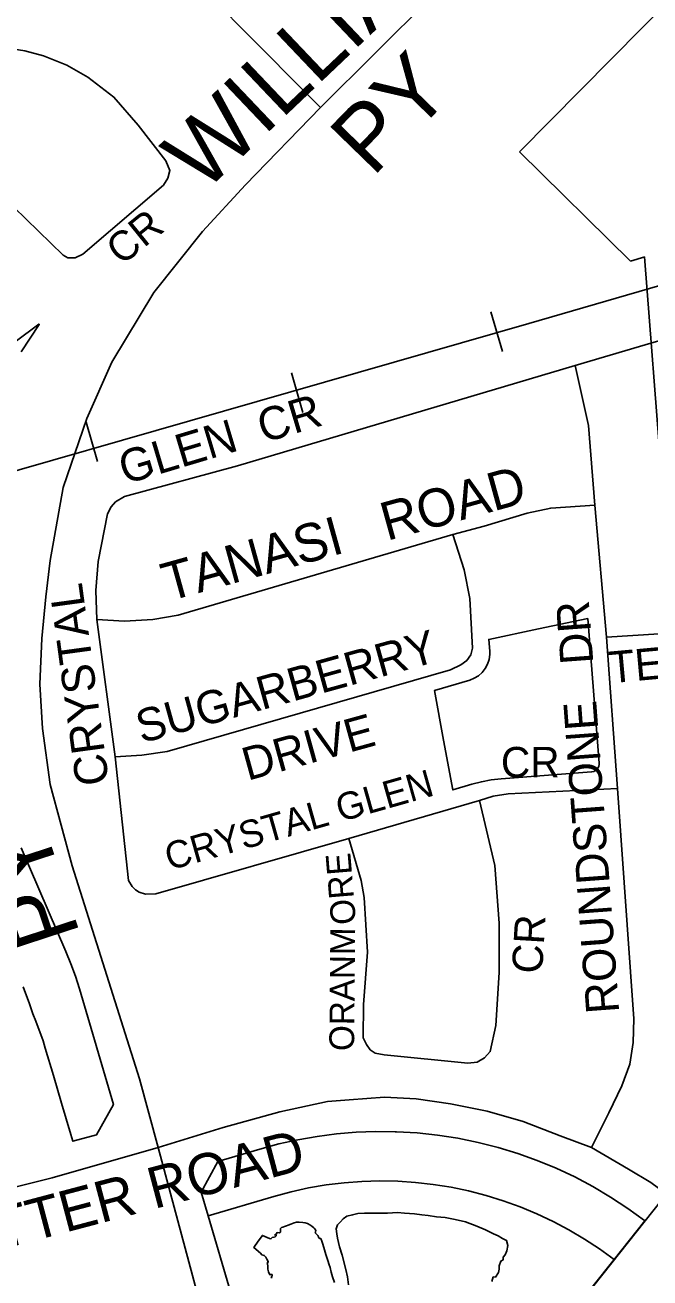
# Model space of a CAD drawing. Extents: x 586326 to 623965, y 4819854 to 4857850.
# Drawn here: x 596152 to 596531, y 4836331 to 4837091 of the extents above; entities that cross this region are included whole.
import ezdxf

# ---------------------------------------------------------------- set-up
doc = ezdxf.new("R2010")
doc.units = 0
for name, color, linetype in [('Hydro ROW', 7, 'Continuous'), ('Lots_Concessions', 7, 'Continuous'), ('Major Rds and Hwys', 7, 'Continuous'), ('Major Rds Lbls', 7, 'Continuous'), ('Minor Rd Lbls', 7, 'Continuous'), ('Minor Rds', 7, 'Continuous'), ('Park Outlines', 7, 'Continuous'), ('Proposed Secondary Rds', 7, 'Continuous'), ('Railways_lbls', 7, 'Continuous'), ('SWM Ponds', 7, 'Continuous')]:
    doc.layers.add(name, color=color, linetype=linetype)

msp = doc.modelspace()

# ---------------------------------------------------------------- linework, layer by layer
at = {"layer": 'Hydro ROW'}
for p, q in [((596591.02, 4837155.19), (596451.94, 4837014.18)), ((596451.94, 4837014.18), (596519.14, 4836947.9)), ((596519.14, 4836947.9), (596527.85, 4836950.48)), ((596563.94, 4836481.91), (596527.79, 4836950.49))]:
    msp.add_line(p, q, dxfattribs=at)
at = {"layer": 'Lots_Concessions'}
msp.add_line((596484.66, 4836310.94), (596595.56, 4836450.63), dxfattribs=at)
at = {"layer": 'Major Rds and Hwys'}
for points in [[(596331.19, 4837041.21), (596397.85, 4837107.73), (596397.99, 4837107.88)], [(596167.02, 4836766.26), (596174.85, 4836810.5), (596189.29, 4836852.37), (596204.48, 4836886.5), (596230.05, 4836928.93), (596259.56, 4836965.95), (596285.65, 4836994.14), (596331.19, 4837041.21)], [(596232.55, 4836410.04), (596221.35, 4836451.78), (596180.34, 4836580.86), (596167.06, 4836630.21), (596162.45, 4836664.21), (596160.75, 4836691.28), (596162.09, 4836718.92), (596164.36, 4836744.15), (596167.02, 4836766.26)], [(596495.59, 4836410.01), (596476.56, 4836417.2), (596454.05, 4836425.89), (596432.2, 4836432.06), (596409.99, 4836436.47), (596389.09, 4836439.47), (596369.91, 4836440.51), (596348.54, 4836439.02), (596335.34, 4836437.93), (596306.45, 4836431.7), (596272.05, 4836422.25), (596232.55, 4836410.04)], [(596232.55, 4836410.04), (596168.29, 4836391.6), (596113.61, 4836377.99), (596057.04, 4836366.29), (595995.22, 4836356.51), (595946.67, 4836348.86)], [(596308.02, 4836117.6), (596304.64, 4836135.97), (596301.26, 4836154.34), (596232.55, 4836410.04)], [(596540.91, 4836381.9), (596531.48, 4836388.76), (596518.05, 4836396.88), (596495.59, 4836410.01)]]:
    msp.add_lwpolyline(points, dxfattribs=at)
at = {"layer": 'Minor Rds'}
for points in [[(596177.73, 4836949.97), (596174.97, 4836951.5), (596144.95, 4836980.58), (596139.29, 4836984.8), (596134.12, 4836987.79), (596129.38, 4836990.25), (596124.6, 4836991.07), (596099.83, 4836996.45), (596095.34, 4836998.71), (596092.74, 4837001.56), (596090.58, 4837006.11), (596090.87, 4837011.35), (596101.52, 4837083.46)], [(596177.73, 4836949.97), (596182.3, 4836949.95), (596186.84, 4836952.02), (596235.73, 4836994.06), (596238.37, 4836998.25), (596239.68, 4837002.86), (596237.16, 4837008.67), (596220.51, 4837030.34), (596205.74, 4837047.39), (596190.01, 4837059.59), (596177.08, 4837066.77), (596163.03, 4837072.54), (596151.75, 4837075.46), (596113.92, 4837081.46), (596101.52, 4837083.46)], [(596485.72, 4836884.52), (596524.79, 4836896.14), (596546.68, 4836902.65), (596603.47, 4836918.93)], [(596195.3, 4836730.51), (596194.8, 4836748.1), (596196.12, 4836765.62), (596201.78, 4836794.53), (596204.11, 4836798.89), (596206.75, 4836801.93), (596212.11, 4836805), (596280.83, 4836823.68), (596485.72, 4836884.52)], [(596497.5, 4836799.75), (596493.68, 4836848.07), (596485.72, 4836884.52)], [(596497.5, 4836799.75), (596470.86, 4836797.99), (596456.6, 4836794.88), (596430.39, 4836787.14), (596411.39, 4836782.09)], [(596504.68, 4836719.75), (596497.5, 4836799.75)], [(596411.39, 4836782.09), (596244.8, 4836732.96), (596229.41, 4836730.47), (596212.19, 4836729.41), (596195.3, 4836730.51)], [(596411.39, 4836782.09), (596418.27, 4836760.48), (596421.72, 4836743.09), (596423.44, 4836713.11), (596422.42, 4836708.99), (596420, 4836705.56), (596416.32, 4836703), (596409.94, 4836699.94), (596238.08, 4836650.36), (596222.77, 4836648.14), (596206.53, 4836647.03)], [(596206.53, 4836647.03), (596195.3, 4836730.51)], [(596621.32, 4836728.19), (596601.41, 4836725.53), (596586.06, 4836724.73), (596552.56, 4836722.68), (596504.68, 4836719.75)], [(596511.26, 4836627.9), (596504.68, 4836719.75)], [(596348.29, 4836597.46), (596231.24, 4836563.94), (596224.81, 4836563.83), (596221.12, 4836564.9), (596218.76, 4836566.33), (596216.74, 4836568.45), (596214.65, 4836572.07), (596206.53, 4836647.03)], [(596511.26, 4836627.9), (596444.95, 4836624.58), (596435.98, 4836623.14), (596427.65, 4836620.6)], [(596495.59, 4836410.01), (596506.16, 4836431.04), (596513.91, 4836447.42), (596518.88, 4836460.51), (596520.77, 4836473.78), (596521.17, 4836488.01), (596511.26, 4836627.9)], [(596427.65, 4836620.6), (596436.91, 4836581.06), (596439.5, 4836546.13), (596439.62, 4836516.15), (596437.47, 4836484.02), (596434.16, 4836468.2), (596430.56, 4836464.36), (596426.13, 4836461.79), (596420.6, 4836461.28), (596369.83, 4836466.23), (596364.28, 4836467.24), (596361.33, 4836469.25), (596359.06, 4836472.53), (596357.04, 4836476.52), (596357.25, 4836496.88), (596359.64, 4836528.53), (596357.58, 4836561.83), (596355.83, 4836571.95), (596348.29, 4836597.46)], [(596427.65, 4836620.6), (596348.29, 4836597.46)]]:
    msp.add_lwpolyline(points, dxfattribs=at)
at = {"layer": 'Park Outlines'}
for points in [[(596149.52, 4836892.78), (596160.43, 4836909.53), (596160.22, 4836909.74), (596132.05, 4836888.75)], [(596150.64, 4836507.47), (596154.43, 4836497.11), (596156.63, 4836491.09), (596158.26, 4836486.78), (596162.81, 4836474.78), (596164.1, 4836470.36), (596169.02, 4836453.67), (596173.93, 4836436.98), (596179.56, 4836417.83), (596180.75, 4836413.8), (596195.23, 4836417.72), (596205.44, 4836436.15), (596184.82, 4836506.23), (596182.38, 4836513.93), (596179.64, 4836521.53), (596176.58, 4836529.01), (596149.41, 4836591.96)], [(596484.63, 4836311.03), (596509.25, 4836342.04), (596500.42, 4836348.47), (596491.3, 4836354.48), (596481.9, 4836360.05), (596472.25, 4836365.18), (596462.38, 4836369.84), (596452.29, 4836374.03), (596442.02, 4836377.75), (596431.58, 4836380.97), (596421, 4836383.7), (596410.31, 4836385.93), (596399.58, 4836387.65), (596388.79, 4836388.86), (596377.95, 4836389.57), (596367.09, 4836389.76), (596356.23, 4836389.45), (596345.4, 4836388.63), (596334.62, 4836387.3), (596323.91, 4836385.47), (596313.3, 4836383.15), (596302.81, 4836380.32), (596262.85, 4836368.56), (596276.43, 4836322.41)]]:
    msp.add_lwpolyline(points, dxfattribs=at)
for points in [[(596493.41, 4836731.12), (596463.31, 4836724.75), (596433.23, 4836718.39), (596433.78, 4836711.25), (596433.82, 4836709.23), (596433.42, 4836706.25), (596432.51, 4836703.37), (596431.11, 4836700.71), (596429.25, 4836698.33), (596427.01, 4836696.32), (596424.44, 4836694.74), (596421.64, 4836693.63), (596400.36, 4836687.36), (596405.85, 4836657.2), (596411.34, 4836627.03), (596422.9, 4836630.44), (596428.78, 4836631.95), (596434.75, 4836633.05), (596440.78, 4836633.73), (596495.59, 4836637.96), (596497.01, 4836638.28), (596498.27, 4836638.99), (596499.27, 4836640.03), (596499.94, 4836641.32), (596500.2, 4836642.74), (596500.19, 4836643.33)], [(596410.31, 4836385.93), (596421, 4836383.7), (596431.58, 4836380.97), (596442.02, 4836377.75), (596452.29, 4836374.03), (596462.38, 4836369.84), (596472.25, 4836365.18), (596481.9, 4836360.05), (596491.3, 4836354.48), (596500.42, 4836348.47), (596509.25, 4836342.04), (596527.9, 4836365.53), (596527.82, 4836365.59), (596527.74, 4836365.65), (596527.66, 4836365.72), (596517.58, 4836373.07), (596507.15, 4836379.94), (596496.41, 4836386.3), (596485.38, 4836392.14), (596474.09, 4836397.45), (596462.55, 4836402.22), (596450.8, 4836406.43), (596438.86, 4836410.08), (596426.76, 4836413.15), (596414.53, 4836415.65), (596402.2, 4836417.56), (596389.78, 4836418.88), (596377.32, 4836419.6), (596376.89, 4836419.62), (596376.45, 4836419.63), (596364.58, 4836419.73), (596352.71, 4836419.29), (596340.88, 4836418.32), (596329.1, 4836416.8), (596317.4, 4836414.76), (596305.81, 4836412.19), (596294.34, 4836409.09), (596268.77, 4836401.56), (596258.62, 4836382.94), (596262.85, 4836368.56), (596302.81, 4836380.32), (596313.3, 4836383.15), (596323.91, 4836385.47), (596334.62, 4836387.3), (596345.4, 4836388.63), (596356.23, 4836389.45), (596367.09, 4836389.76), (596377.95, 4836389.57), (596388.79, 4836388.86), (596399.58, 4836387.65)]]:
    msp.add_lwpolyline(points, close=True, dxfattribs=at)
at = {"layer": 'Proposed Secondary Rds'}
msp.add_lwpolyline([(596331.19, 4837041.21), (596280.91, 4837091.39), (596273.96, 4837098.83)], dxfattribs=at)
at = {"layer": 'Railways_lbls'}
for p, q in [((596434.48, 4836917.1), (596441.48, 4836893.1)), ((596313.48, 4836880.1), (596320.48, 4836856.1)), ((596188.87, 4836850.25), (596195.87, 4836826.25))]:
    msp.add_line(p, q, dxfattribs=at)
msp.add_lwpolyline([(598326.48, 4837460.1), (597795.48, 4837305.1), (597795.48, 4837304.1), (597377.48, 4837181.1), (597375.48, 4837181.1), (596913.48, 4837043.1), (596909.48, 4837041.1), (596457.48, 4836910.1), (595921.93, 4836756.32)], dxfattribs=at)
at = {"layer": 'SWM Ponds'}
for points in [[(596339.69, 4836328.2), (596338.38, 4836331.52), (596337.59, 4836334.33), (596336.9, 4836337.28), (596336.33, 4836338.73), (596335.49, 4836341.42), (596334.37, 4836345.18), (596333.63, 4836348), (596332.57, 4836351.28), (596331.97, 4836353.19), (596331.3, 4836354.79), (596330.65, 4836354.71), (596330.11, 4836355.18), (596329.87, 4836355.9), (596329.57, 4836356.67), (596328.6, 4836357.48), (596327.89, 4836358.15), (596328.06, 4836358.92), (596328.28, 4836359.6), (596327.67, 4836360.67), (596326.98, 4836361.36), (596325.91, 4836362.31), (596324.68, 4836363.06), (596323.17, 4836363.86), (596321.78, 4836364.41), (596320.43, 4836364.46), (596318.14, 4836364.74), (596316.6, 4836364.62), (596315.03, 4836364.24), (596313.2, 4836363.48), (596311.56, 4836362.95), (596310.53, 4836362.52), (596309.32, 4836362.13), (596308.23, 4836361.76), (596307.51, 4836361.46), (596306.88, 4836360.78), (596306.89, 4836359.71), (596306.78, 4836358.67), (596306.17, 4836358.24), (596304.71, 4836358.42), (596304.22, 4836357.52), (596303.36, 4836356.96), (596304.31, 4836356.64), (596303.64, 4836355.89), (596302.79, 4836355.53), (596301.72, 4836355.41), (596300.98, 4836354.6), (596300.12, 4836354.74), (596295.87, 4836356.67), (596293.29, 4836353.24), (596290.68, 4836349.28), (596294.61, 4836345.9), (596295.57, 4836344.94), (596296.94, 4836344.51), (596298.03, 4836343.45), (596298.48, 4836342.24), (596299.43, 4836340.86), (596299.34, 4836340.34), (596298.83, 4836340.18), (596298.94, 4836339.54), (596299.23, 4836337.81), (596299.06, 4836336.29), (596299.64, 4836334.5), (596300.33, 4836332.79), (596300.88, 4836332.94), (596301.6, 4836332.98), (596301.83, 4836332.31), (596301.59, 4836331.53), (596301.26, 4836331.45), (596301.46, 4836330.68)], [(596435.17, 4836328.64), (596435.93, 4836331.45), (596437.26, 4836331.31), (596439.12, 4836334.16), (596439.47, 4836336.21), (596439.63, 4836338.25), (596440.59, 4836341.08), (596441.9, 4836341.85), (596441.99, 4836343.57), (596443.15, 4836344.82), (596444.24, 4836347.37), (596444.85, 4836350.66), (596443.97, 4836353.67), (596441.62, 4836354.79), (596438.91, 4836356.37), (596436.03, 4836357.73), (596431.21, 4836360.06), (596425.92, 4836362.23), (596419.04, 4836364.9), (596412.83, 4836366.35), (596406.75, 4836367.52), (596401.47, 4836367.88), (596396.54, 4836368.68), (596392.56, 4836369.1), (596388.06, 4836369.75), (596382.16, 4836370.24), (596377.9, 4836370.52), (596371.79, 4836370.27), (596366.05, 4836370.27), (596361.24, 4836370.09), (596357.91, 4836370.18), (596353.81, 4836369.98), (596350.6, 4836369.08), (596347.05, 4836368.44), (596344.85, 4836366.76), (596343.26, 4836364.96), (596341.47, 4836363.13), (596340.57, 4836360.6), (596341.02, 4836357.74), (596341.45, 4836355.07), (596342.61, 4836349.68), (596344.24, 4836344.65), (596346.5, 4836336.07), (596347.46, 4836331.56), (596348.07, 4836326.6)]]:
    msp.add_lwpolyline(points, dxfattribs=at)

# ---------------------------------------------------------------- texts
at = {"layer": 'Major Rds Lbls'}
for s, height, rotation, p in [('WILLIAMS', 40.002, 43.57309, (596259.95, 4836988.54)), ('PY', 40.002, 45.83466, (596362.74, 4836998.39)), ('PY', 40.002, 108.12781, (596185.41, 4836539.41)), ('POTTER ROAD', 25.002, 14.83402, (596090.01, 4836335.51))]:
    msp.add_text(s, height=height, rotation=rotation, dxfattribs=at).set_placement(p)
at = {"layer": 'Minor Rd Lbls'}
for s, height, rotation, p in [('CR', 18, 38.97224, (596210.39, 4836944.79)), (' GLEN  CR', 20.02, 16.66346, (596205.24, 4836810.12)), ('TANASI   ROAD', 23.1755, 15.48037, (596238.62, 4836741.28)), ('CRYSTAL', 20.02, 97.74478, (596202.87, 4836630.97)), ('ROUNDSTONE   DR', 20.0032, 94.23299, (596512.42, 4836491.97)), ('SUGARBERRY', 20.02, 15.48037, (596222.44, 4836655.18)), ('  TERRACE', 19.227, 5.17653, (596492.76, 4836690.42)), ('DRIVE', 20.02, 15.48037, (596286.87, 4836632.5)), ('CR', 18.435, 0.16891, (596440.63, 4836634.64)), ('CRYSTAL GLEN ', 16.4954, 15.81884, (596239.42, 4836578.08)), ('ORE', 15.063, 94.68022, (596352.72, 4836545.78)), ('CR', 18.435, 86.59335, (596465.58, 4836515.19)), ('ORANM', 15.063, 89.46986, (596351.47, 4836468.52))]:
    msp.add_text(s, height=height, rotation=rotation, dxfattribs=at).set_placement(p)

doc.saveas('drawing.dxf')
